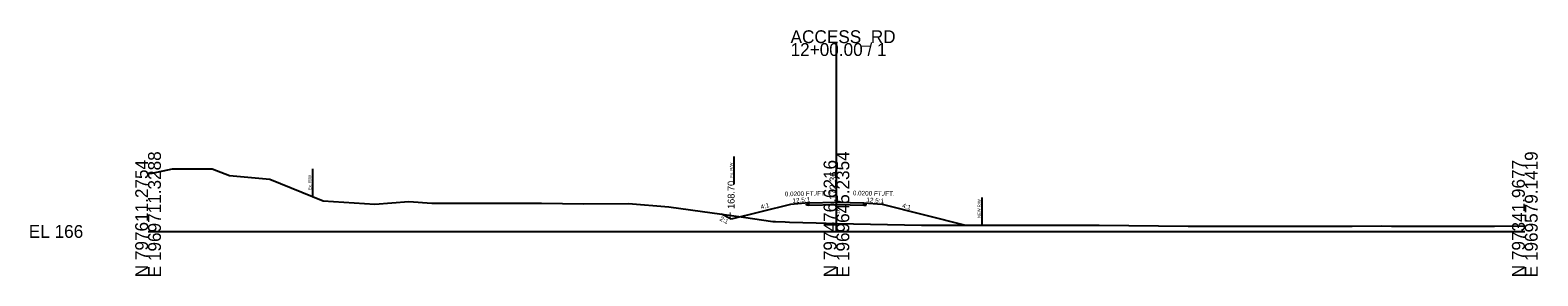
# Model space of a CAD drawing. Extents: x 27306 to 1891059, y 5381 to 776288.
# Drawn here: x 27306 to 27634.5, y 6880.7 to 6934.4 of the extents above; entities that cross this region are included whole.
import ezdxf

# ---------------------------------------------------------------- set-up
doc = ezdxf.new("R2010")
doc.units = 0
for name, color, linetype in [('RD_EX_BldgApp', 7, 'Continuous'), ('RD_EX_H2O_BlueLn', 7, 'Continuous'), ('RD_EX_RailRoad', 7, 'Continuous'), ('RD_HC_Cl', 7, 'Continuous'), ('RD_HC_Data', 7, 'Continuous'), ('RD_HC_Data_Tic', 7, 'Continuous'), ('RD_HC_TX_Sta50', 7, 'Continuous'), ('RD_PD_ALT2_CL', 7, 'Continuous'), ('RD_PD_ALT3_CL', 7, 'Continuous'), ('RD_PD_ALT5_CL', 7, 'Continuous'), ('RD_PD_Final_Cl', 7, 'Continuous'), ('RD_PD_Final_TrvlWay', 7, 'Continuous'), ('RD_PD_MedBWall', 7, 'Continuous'), ('RD_TX_Misc2', 7, 'Continuous'), ('RD_TX_RoadID', 7, 'Continuous')]:
    doc.layers.add(name, color=color, linetype=linetype)

msp = doc.modelspace()

# ---------------------------------------------------------------- linework, layer by layer
at = {"layer": 'RD_EX_H2O_BlueLn'}
for p, q in [((27475.61, 6896.67), (27471.61, 6896.35)), ((27487.61, 6896.68), (27491.61, 6896.36))]:
    msp.add_line(p, q, dxfattribs=at)
at = {"layer": 'RD_EX_RailRoad'}
for p, q in [((27475.11, 6896.41), (27475.61, 6896.42)), ((27475.11, 6896.16), (27475.11, 6896.41)), ((27475.61, 6896.17), (27475.11, 6896.16)), ((27475.61, 6896.42), (27475.61, 6896.67)), ((27475.61, 6896.17), (27481.65, 6896.3)), ((27481.65, 6896.3), (27487.61, 6896.18)), ((27487.61, 6896.43), (27487.61, 6896.68)), ((27488.11, 6896.42), (27487.61, 6896.43)), ((27487.61, 6896.18), (27488.11, 6896.17)), ((27488.11, 6896.17), (27488.11, 6896.42))]:
    msp.add_line(p, q, dxfattribs=at)
at = {"layer": 'RD_HC_Cl'}
for p, q in [((27481.65, 6890.44), (27481.65, 6931.54)), ((27331.65, 6890.44), (27481.65, 6890.44)), ((27481.65, 6890.44), (27631.65, 6890.44))]:
    msp.add_line(p, q, dxfattribs=at)
at = {"layer": 'RD_PD_ALT5_CL'}
for p, q in [((27471.61, 6896.35), (27458.73, 6893.14)), ((27491.61, 6896.36), (27509.76, 6891.82)), ((27458.73, 6893.14), (27456.61, 6894.2))]:
    msp.add_line(p, q, dxfattribs=at)
at = {"layer": 'RD_PD_Final_Cl'}
msp.add_lwpolyline([(27331.65, 6903.16), (27332.54, 6903.15), (27336.95, 6904.14), (27345.6, 6904.14), (27349.41, 6902.64), (27358.17, 6901.88), (27369.82, 6897.11), (27381.07, 6896.43), (27388.44, 6896.99), (27393.49, 6896.6), (27417.38, 6896.6), (27426.54, 6896.49), (27436.3, 6896.51), (27445.12, 6895.8), (27461.42, 6893.53), (27467.82, 6892.64), (27468.35, 6892.64), (27470.48, 6892.52), (27471.42, 6892.48), (27477.22, 6892.3), (27481.65, 6892.21), (27500.16, 6891.82), (27528.43, 6891.82), (27533.58, 6891.82), (27535.33, 6891.81), (27538.91, 6891.78), (27558.3, 6891.57), (27567, 6891.59), (27594.06, 6891.62), (27600.42, 6891.65), (27602.59, 6891.62), (27607.01, 6891.62), (27625.01, 6891.61), (27631.65, 6891.64)], dxfattribs=at)
at = {"layer": 'RD_PD_Final_TrvlWay'}
for p, q in [((27459.32, 6906.79), (27459.32, 6900.79)), ((27367.48, 6904.08), (27367.48, 6898.08))]:
    msp.add_line(p, q, dxfattribs=at)
at = {"layer": 'RD_PD_MedBWall'}
for p, q in [((27475.61, 6896.67), (27481.65, 6896.8)), ((27481.65, 6896.8), (27487.61, 6896.68))]:
    msp.add_line(p, q, dxfattribs=at)
at = {"layer": 'RD_TX_Misc2'}
for p, q in [((27475.61, 6896.67), (27471.61, 6896.35)), ((27487.61, 6896.68), (27491.61, 6896.36))]:
    msp.add_line(p, q, dxfattribs=at)
at = {"layer": 'RD_TX_RoadID'}
msp.add_line((27513.34, 6897.82), (27513.34, 6891.82), dxfattribs=at)

# ---------------------------------------------------------------- texts
at = {"layer": 'RD_EX_BldgApp'}
msp.add_text('167.77', height=0.8, rotation=90, dxfattribs=at).set_placement((27482.35, 6894.24))
at = {"layer": 'RD_HC_Cl'}
for s, p in [('ACCESS_RD', (27471.65, 6931.54)), ('12+00.00 / 1', (27471.65, 6928.74)), ('EL 166', (27305.65, 6889.04))]:
    msp.add_text(s, height=2.8, dxfattribs=at).set_placement(p)
for s, p in [('N 797611.2754', (27331.65, 6880.44)), ('E 1969711.3288', (27334.45, 6880.44)), ('N 797476.6216', (27481.65, 6880.44)), ('E 1969645.2354', (27484.45, 6880.44)), ('N 797341.9677', (27631.65, 6880.44)), ('E 1969579.1419', (27634.45, 6880.44))]:
    msp.add_text(s, height=2.8, rotation=90, dxfattribs=at).set_placement(p)
at = {"layer": 'RD_HC_Data'}
msp.add_text(' 172.36', height=1.5, rotation=90, dxfattribs=at).set_placement((27481.65, 6896.8))
at = {"layer": 'RD_HC_Data_Tic'}
for rotation, p in [(4.5739, (27472.11, 6896.65)), (355.4261, (27488.15, 6896.88))]:
    msp.add_text('12.5:1', height=1, rotation=rotation, dxfattribs=at).set_placement(p)
at = {"layer": 'RD_HC_TX_Sta50'}
for s, rotation, p in [('0.0200 FT./FT.', 1.1458, (27470.4, 6898.11)), ('0.0200 FT./FT.', 358.8542, (27485.21, 6898.34)), ('4:1', 15.5821, (27465.26, 6895.26)), ('4:1', 344.4179, (27495.88, 6895.67)), ('2:1', 333.435, (27456.09, 6892.9))]:
    msp.add_text(s, height=1, rotation=rotation, dxfattribs=at).set_placement(p)
at = {"layer": 'RD_PD_ALT2_CL'}
msp.add_text('168.70', height=1.5, rotation=90, dxfattribs=at).set_placement((27459.44, 6895.35))
at = {"layer": 'RD_PD_ALT3_CL'}
msp.add_text('L', height=1.5, dxfattribs=at).set_placement((27458.23, 6893.14))
at = {"layer": 'RD_PD_Final_TrvlWay'}
for p in [(27367.23, 6899.46), (27459.07, 6902.18)]:
    msp.add_text('Ex. R/W ', height=0.65, rotation=90, dxfattribs=at).set_placement(p)
at = {"layer": 'RD_TX_RoadID'}
msp.add_text('NEW R/W ', height=0.65, rotation=90, dxfattribs=at).set_placement((27513.07, 6893.38))

doc.saveas('drawing.dxf')
